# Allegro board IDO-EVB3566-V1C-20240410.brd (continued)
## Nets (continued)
PWM5_MIPI: M1.150(PWM5/SPI0_CS1_M0/UART0_RTSN/GPI) R49.2 U6.4(EN)
PWM6_OUT: D45.2 D45.9 J31.4 M1.148(PWM6/SPI0_MISO_M0/GPIO0_C5_D)
PWM7_IR: D45.1 D45.10 J31.2 M1.151(PWM7_IR/SPI0_CS0_M0/GPIO0_C6_D)
RECOVERY_KEY: C33.2 D5.1(I/O2) R25.2 SW4.3
RESETN: D82.2 D82.9 J46.3 M1.222(RESETN) R1231.2
RMII_CLK_: R1224.2 U11.15(TXC)
RMII_CLK_CTL: R1214.1 U11.12(RXD3/CLK_CTL)
RMII_RST_: C384.2 R1201.2 R1202.1 U11.21(PHYRSTB)
RN: D81.1 U11.6(MDI1-) U23.1(TD+)
RP: D81.3 U11.5(MDI1+) U23.3(TD-)
RXD0: R1206.1 U11.9(RXD0)
RXD1: R1205.1 R1215.1 U11.10(RXD1)
RXDV: R1213.1 U11.8(RXDV)
RXN: J12.6(RX-) U23.16(TX+)
RXP: J12.3(RX+) U23.14(TX-)
S0_RX: D43.1 D43.10 J42.2 R184.2 U22.13(R1IN)
S0_TX: D43.2 D43.9 J42.3 R183.2 U22.14(T1OUT)
S5_RX: D43.4 D43.7 J43.2 R186.2 U22.8(R2IN)
S5_TX: D43.5 D43.6 J43.3 R185.2 U22.7(T2OUT)
S7_RX: J40.2 R174.2 U21.13(R1IN)
S7_TX: J40.3 R173.2 U21.14(T1OUT)
S9_RX: J41.2 R176.2 U21.8(R2IN)
S9_TX: J41.3 R175.2 U21.7(T2OUT)
SARADC_VIN0/RECOVERY: M1.164(SARADC_VIN0/RECOVERY) R25.1
SARADC_VIN1: D82.4 D82.7 J46.4 M1.231(SARADC_VIN1)
SARADC_VIN2: D82.5 D82.6 J46.5 M1.165(SARADC_VIN2)
SDMMC0_CLK_: C155.2 D34.1 D34.10 J21.5(CLK) R160.2
SDMMC0_CLK_SD: M1.37(SDMMC0_CLK/TEST_CLKOUT/UART5_TX) R160.1
SDMMC0_CMD_SD: D33.4 D33.7 J21.3(CMD) M1.33(PWM10_M1/SDMMC0_CMD/UART5_RX_M0)
SDMMC0_D0_SD: D34.2 D34.9 J21.7(DATA0) M1.35(PWM8_M1/SDMMC0_D0/UART2_TX_M1/U)
SDMMC0_D1_SD: D34.4 D34.7 J21.8(DATA1) M1.32(PWM9_M1/SDMMC0_D1/UART2_RX_M1/U)
SDMMC0_D2_SD: D33.1 D33.10 J21.1(DATA2) M1.36(SDMMC0_D2/ARM_JTAG_TCK/UART5_CT)
SDMMC0_D3_SD: D33.2 D33.9 J21.2(CD/DATA3) M1.34(SDMMC0_D3/ARM_JTAG_TMS/UART5_RT)
SDMMC0_DET_L_SD: D34.5 D34.6 J21.9(CD) M1.163(SDMMC0_DET/SATA_CP_DET/GPIO0_A4) R344.2
SDMMC1_CLK_WIFI: M1.49(UART9_TX_M0/SDMMC1_CLK/GPIO2_B0) R67.1
SDMMC1_CMD_WIFI: M1.54(UART9_RX_M0/SDMMC1_CMD/GPIO2_A7) R66.2 U10.16(SDIO_DATA_CMD)
SDMMC1_D0_WIFI: M1.51(UART6_RX_M0/SDMMC1_D0/GPIO2_A3_) R65.2 U10.18(SDIO_DATA_0)
SDMMC1_D1_WIFI: M1.50(UART6_TX_M0/SDMMC1_D1/GPIO2_A4_) U10.19(SDIO_DATA_1)
SDMMC1_D2_WIFI: M1.55(UART7_RX_M0/SDMMC1_D2/GPIO2_A5_) U10.14(SDIO_DATA_2)
SDMMC1_D3_WIFI: M1.48(UART7_TX_M0/SDMMC1_D3/GPIO2_A6_) U10.15(SDIO_DATA_3)
SPI3_CLK_M1_OUT: D44.1 D44.10 J31.1 M1.206(PWM14_M1/SPI3_CLK_M1/I2S3_MCLK_)
SPI3_CS0_M1_OUT: D44.5 D44.6 J31.7 M1.201(PWM13_M1/SPI3_CS0_M1/SATA0_ACT_)
SPI3_MISO_M1_OUT: D44.4 D44.7 J31.5 M1.202(PWM12_M1/SPI3_MISO_M1/SATA1_ACT)
SPI3_MOSI_M1_OUT: D44.2 D44.9 J31.3 M1.204(PWM15_IR_M1/SPI3_MOSI_M1/I2S3_S)
SYS_LED_H: M1.69(ISP_FLASHTRIGOUT/EBC_SDCE0/GMAC) R415.2 R1227.1
TN: D81.4 U11.4(MDI0-) U23.6(RD+)
TP: D81.6 U11.3(MDI0+) U23.8(RD-)
TP1_INT: D18.2 D18.9 J8.5 J9.3 R44.2
TP1_RST: D18.1 D18.10 J8.4 J9.2 R43.2
TP1_SCL: D18.4 D18.7 J8.6 J9.4 R41.2 R42.1
TP1_SDA: D18.5 D18.6 J8.7 J9.5 R39.2 R40.1
TXN: J12.2(TX-) U23.11(RX+)
TXP: J12.1(TX+) U23.9(RX-)
UART0_RX: M1.157(PWM1_M0/GPUAVS/UART0_RX/GPIO0_C) R184.1 R189.1
UART0_TX: M1.156(PWM2_M0/NPUAVS/UART0_TX/MCU_JTA) R183.1 U22.11(T1IN)
UART1_CTSN_M0_WIFI: M1.39(SPI1_MISO_M0/UART1_CTSN_M0/GPIO) R69.1 U10.41(UART_RTS_N)
UART1_RTSN_M0_WIFI: M1.40(SPI1_CLK_M0/UART1_RTSN_M0/GPIO2) U10.44(UART_CTS_N)
UART1_RX_M0_WIFI: M1.47(UART1_RX_M0/GPIO2_B3_U) U10.42(UART_TXD)
UART1_TX_M0_WIFI: M1.46(UART1_TX_M0/GPIO2_B4_U) U10.43(UART_RXD)
UART2_RX_M0_DEBUG: M1.153(UART2_RX_M0_DEBUG/GPIO0_D0_U) R161.1
UART2_TX_M0_DEBUG: M1.152(UART2_TX_M0_DEBUG/GPIO0_D1_U) R162.1
UART5_RX_M1: M1.80(VOP_BT1120_D15/SPI1_CLK_M1/UART) R186.1 R190.1
UART5_TX_M1: M1.81(VOP_BT1120_D14/SPI1_MISO_M1/UAR) R185.1 U22.10(T2IN)
UART7_RX_M2: M1.73(CIF_D13/EBC_SDDO13/GMAC1_RXCLK_) R174.1 R178.1
UART7_TX_M2: M1.62(CIF_D12/EBC_SDDO12/GMAC1_RXD3_M) R173.1 U21.11(T1IN)
UART9_RX_M2: M1.71(CIF_D15/EBC_SDDO15/GMAC1_TXD1_M) R176.1 R177.1
UART9_TX_M2: M1.61(CIF_D14/EBC_SDDO14/GMAC1_TXD0_M) R175.1 U21.10(T2IN)
USB3_HOST1_DM: M1.16(USB_HOST1_DM) R124.1
USB3_HOST1_DM_2: D28.2(I/O1) J16.2(D-) R124.2
USB3_HOST1_DP: M1.17(USB_HOST1_DP) R126.1
USB3_HOST1_DP_2: D29.1(I/O2) J16.3(D+) R126.2
USB3_HOST1_SSRXN: M1.14(USB3_HOST1_SSRXN/SATA1_RXN) R127.1
USB3_HOST1_SSRXP: M1.15(USB3_HOST1_SSRXP/SATA1_RXP) R128.1
USB3_HOST1_SSTXN: C125.1 M1.12(USB3_HOST1_SSTXN/SATA1_TXN)
USB3_HOST1_SSTXP: C126.1 M1.13(USB3_HOST1_SSTXP/SATA1_TXP)
USB3_HOST1SSRXN: D30.1 D30.10 J16.5(SSRX-) R127.2
USB3_HOST1SSRXP: D30.2 D30.9 J16.6(SSRX+) R128.2
USB3_HOST1SSTXN: C125.2 D30.4 D30.7 J16.8(SSTX-)
USB3_HOST1SSTXP: C126.2 D30.5 D30.6 J16.9(SSTX+)
USB_HOST2_DM: M1.101(USB_HOST2_DM) R325.1
USB_HOST2_DM_: D46.1(I/O2) J39.2 R325.2
USB_HOST2_DP: M1.102(USB_HOST2_DP) R326.1
USB_HOST2_DP_: D47.1(I/O2) J39.3 R326.2
USB_HOST3_DM: M1.99(USB_HOST3_DM) R299.1
USB_HOST3_DP: M1.100(USB_HOST3_DP) R298.1
USB_OTG0_DM: M1.20(USB_OTG0_DM) R116.1
USB_OTG0_DM_2: D26.2(I/O1) J15.2(DATA+) R116.2
USB_OTG0_DP: M1.21(USB_OTG0_DP) R118.1
USB_OTG0_DP_2: D27.1(I/O2) J15.3(DATA-) R118.2
USB_OTG0_ID: M1.18(USB_OTG0_ID) Q5.3(DRAIN)
USB_OTG0_VBUSDET: M1.19(USB_OTG0_VBUSDET) R120.2 R121.1 R123.2
VOLN: C193.1 J25.4 L22.2
VOLP: C192.1 J25.3 L21.2
VORN: C198.1 J25.2 L24.2
VORP: C197.1 J25.1 L23.2
WIFI1T1R_CLK: C76.2 R67.2 U10.17(SDIO_DATA_CLK)
WIFI1T1R_XTAL_IN: C78.1 U10.10(XTAL_IN) XT2.3
WIFI1T1R_XTAL_OUT: R68.2 U10.11(XTAL_OUT)
WIFIBT_32KIN_1T1R: R73.2 R74.2 U10.24(LPO)
N17053074: C77.2 C79.2 U10.2(WL_BT_ANT)
N17053234: C77.1 C80.2 J11.2(SIG)
N19277328: C181.2 U22.1(C1+)
N19277330: C181.1 U22.3(C1-)
N19277334: C182.2 U22.4(C2+)
N19277336: C182.1 U22.5(C2-)
N19277340: C183.2 U22.2(V+)
N19277344: C184.2 U22.6(V-)
N19354508: C394.1 R63.1 R64.2 U9.4(ADJ)
N19356461: R56.1 R57.2 U7.4(ADJ)
N19357233: R59.1 R60.2 U8.4(ADJ)
N19781253: C176.2 U21.1(C1+)
N19781255: C176.1 U21.3(C1-)
N19781259: C177.2 U21.4(C2+)
N19781261: C177.1 U21.5(C2-)
N19781265: C178.2 U21.2(V+)
N19781269: C179.2 U21.6(V-)
N19781407: R177.2 U21.9(R2OUT)
N20037713: R178.2 U21.12(R1OUT)
N20144283: R189.2 U22.12(R1OUT)
N20144293: R190.2 U22.9(R2OUT)
N67159131: R136.1 U15.3(OCB)
N68563646: C30.2 U5.1(OSCI) XT1.2
N68563661: C31.2 U5.2(OSCO) XT1.1
N68693421: R148.1 U17.3(OCB)
N68696061: R153.1 U18.3(OCB)
N68696295: R158.1 U19.3(OCB)
N69227462: C397.2 R5.2 R7.2 U1.5(EN)
N69227513: C6.1 R3.1 R8.2 U1.6(FB)
N69227900: L3.1 U3.3(SW)
N69227918: R10.1 R12.2 U3.5(FB)
N69724413: R11.2 U3.1(EN)
N69863572: C81.2 R68.1 XT2.1
N69864462: C90.2 C91.2 L6.2 U10.23(VIN_LDO)
N69864477: L6.1 U10.21(VIN_LDO_OUT)
N69911722: R48.2 U6.3(FB)
N69911786: C53.2 J8.17 R38.2
N69912226: D23.A L5.2 U6.1(LX)
N69966336: J12.12(LEDG-) R1210.2
N69966774: C2.1 L1.1 U1.2(LX)
N69967080: C2.2 U1.4(BS)
N70130938: C388.2 U11.29(DVDD10OUT)
N70266506: J12.9(LEDY+) R1211.2
N70266836: R1203.1 U11.19(TXD3)
N70527306: D35.2(I/O1) J22.1 R161.2
N70527342: D36.2(I/O1) J22.2 R162.2
N70531034: D12.C R32.1 R34.1
N70572735: C185.2 J31.9 R195.2 R196.2
N70591036: R6.2 U2.5(EN)
N70591050: C3.1 L2.1 U2.2(LX)
N70591060: C13.1 R4.1 R9.2 U2.6(FB)
N70591176: C3.2 U2.4(BS)
N70593664: C61.1 J9.1 R46.2 R47.2
N70626310: M1.57(CAM_CLKOUT0/EBC_SDCE1/GMAC1_RXD) R16.2
N70633183: R129.2 U14.3(OCB)
N70633229: R122.2 U13.3(OCB)
N70633628: Q5.1(GATE) R117.1 R119.1
N70648039: C159.2 D38.1(I/O2) J34.5(L-COM) R164.1 R166.2
N70649018: C161.2 R169.2 R170.1
N70649944: C158.2 R163.2 R167.2
N70663154: R14.1 U4.4(EN)
N70663167: R1220.2 U4.3(OCB)
N70672743: C186.2 U24.2(BYPASS)
N70672808: C187.2 R197.1
N70672810: R197.2 U24.3(INP)
N70672945: C188.2 R198.1
N70672947: R198.2 U24.4(INN)
N70673300: L21.1 U24.8(VOP)
N70673587: L22.1 U24.5(VON)
N70674127: C194.2 U25.2(BYPASS)
N70674131: C195.2 R200.1
N70674133: R200.2 U25.3(INP)
N70674155: C196.2 R201.1
N70674157: R201.2 U25.4(INN)
N70674204: L23.1 U25.8(VOP)
N70674215: L24.1 U25.5(VON)
N70676752: R295.2 U26.8(RREF)
N70676766: R301.1 U26.25(OVCUR1#)
N70676768: R300.1 U26.24(OVCUR2#)
N70676770: R293.1 U26.23(PGANG)
N70676772: R294.1 U26.22(PSELF)
N70676774: R292.1 U26.19(OVCUR4#)
N70676824: R302.1 U26.20(OVCUR3#)
N70676921: R296.2 U26.5(AVDD/NC#5)
N70676923: R297.2 U26.9(AVDD/NC#9)
N70708323: R327.1 U27.3(OCB)
N70802303: C371.2 U23.7(CT2)
N70802422: C372.2 U23.2(CT1)
N70802644: R1229.1 U23.10(CT3)
N70803761: R1228.1 U23.15(CT4)
N70846219: R1207.1 U11.1(RSET)
N70854426: R1221.2 U7.3(EN) U8.3(EN) U9.3(EN)
N70857622: LED3.1(+) R19.2
N70857637: LED3.2(-) Q10.3(DRAIN)
N70857653: Q10.1(GATE) R1227.2
N70869941: C396.2 R1228.2
N70869956: C395.2 R1229.2
N70885563: J7.4 R1230.2
N70966122: R231.2 R232.1 U28.3(VCC)
N70966143: D86.A R1231.1 U28.2(RSET#)
N76750177: C385.2 U11.2(AVDD100UT)

Pads without a net: D33 5 6; D81 5; HOLE2 1; HOLE3 1; HOLE4 1; J5 1 7 30; J6 14; J7 1 5 6 7 23 24 26 27 29 30 34 37; J8 3 8 12 13 14 15 35 40; J12 4 5 7 8; J34 6; LED3 3; M1 1 2 3 4 5 6 24 25 26 27 56 90 91 95 96 97 98 103 104 173 174 175 177 178 179 183 184 185 189 190 191 193 194 195 203 207 208 209 210 214 219 220 221 227 230 234 235 236 237; MARK1 1; MARK2 1; MARK3 1; MARK4 1; U5 3 7; U10 4 5 8 29 30 32 35 37 38 39 40 45 46 47; U11 13 18 27; U23 4 5 12 13; U26 18 26

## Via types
v1: diameter 0.55, hole 0.3, TOP to BOTTOM, 1211 vias

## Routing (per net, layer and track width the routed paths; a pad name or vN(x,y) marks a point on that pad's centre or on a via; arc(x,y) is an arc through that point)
GND: length 1029.8
  TOP w0.127: v1(85.22,10.41) 85.22,9.78 84.96,9.53 81.03,9.53 80.78,9.77 v1(80.78,12.2) ; v1(62.74,53.21) 62.87,53.21 64.3,54.65 66.71,54.65 66.8,54.74 66.8,63.3 69.07,65.57 v1(69.47,65.57) 69.51,65.53 84.87,65.53 86.14,66.8 v1(87.96,66.8) ; v1(83.74,56.11) 83.64,56 83.64,55.88 82.56,54.8 81.69,54.8 79.22,52.34 v1(79.22,51.31) ; v1(77.34,41.66) 77.09,41.91 77.09,43.95 77,44.05 77,44.43 77.09,44.52 77.09,46.74 77.41,47.05 77.41,47.27 77.9,47.76 78.12,47.76 79.17,48.82 v1(79.17,49.68) ; C81.1 80.59,48.01 80.24,48.01 79.83,48.41 79.76,48.41 v1(79.76,51.69) 79.76,52.51 80.2,52.96 83.95,52.96 84.08,52.82 84.08,49.28 v1(83.44,48.64) ; v1(64.6,52.87) 64.6,53.06 65.28,53.73 67.09,53.73 67.75,54.4 67.75,62.96 69.07,64.28 85.16,64.28 85.86,64.98 86.87,64.98 87.68,65.79 88.39,65.79 89.03,65.15 90.54,65.15 v1(91.18,65.79) ; v1(19.01,7.83) 19.1,7.92 19.1,10.13 18.81,10.42 18.79,10.42 v1(18.79,10.47) 18.74,10.52 17.09,10.52 16.87,10.29 v1(16.73,10.29) 16.47,10.54 14.96,10.54 14.61,10.19 v1(14.61,10.16) 14.32,10.44 12.6,10.44 12.32,10.16 v1(12.32,10.06) 12.32,7.9 12.62,7.59 13.19,7.59 13.57,7.21 J5.29 ; 71.75,56.64 71.76,56.64 71.76,60.75 v1(71.97,60.96)
  TOP w0.305: J8.11 49.58,7.59 v1(49.38,7.8) ; J5.23 v1(16.57,7.69) ; J8.22 44.08,7.34 43.67,7.75 v1(43.31,7.75) ; v1(82.84,4.64) 82.83,4.65 82.83,5.59 83.05,5.8 J7.19 ; v1(19.01,7.83) 18.5,7.83 18.07,7.4 J5.20 ; J8.28 41.08,5.97 41.61,5.44 v1(41.98,5.44) ; J6.5 v1(79.98,62.43) ; J6.2 v1(78.48,62.34) ; J6.11 v1(82.98,62.49) ; J8.25 42.58,7.76 v1(42.62,7.8) ; J8.31 v1(39.58,5.65) ; J6.17 v1(85.98,62.64) ; J5.29 v1(13.57,5.61) ; v1(62.73,8.4) 62.38,8.04 J9.6 ; J6.8 v1(81.48,62.5) ; J5.26 v1(15.07,7.7)
  TOP w0.381: v1(20.64,17.74) 20.11,17.21 19.81,17.21 ; R199.1 v1(78.71,31.14) ; v1(95.12,25.02) D32.3 D32.8 ; M1.170 72.69,48.06 v1(72.34,48.41) ; C298.1 88.6,21.21 88.74,21.06 v1(88.95,21.06) ; D44.8 D44.3 v1(10.92,17.91) ; v1(93.6,35.81) 93.47,35.69 D47.2 ; v1(10.79,14.73) D45.3 D45.8 ; v1(91.18,65.79) R165.1 ; U10.36 v1(93.69,38.32) ; v1(26.85,31.52) 27.03,31.7 27.03,32.64 26.6,33.06 M1.192 26.17,32.65 26.17,31.62 v1(25.96,31.41) ; C198.2 89,28.54 89,29.08 v1(88.98,29.11) 89.15,29.29 C193.2 ; C76.1 77.55,41.86 v1(77.34,41.66) ; v1(85.22,10.41) 85.21,10.4 XT5.2 ; v1(11.56,25.65) 11.87,25.34 R12.1 ; v1(51.31,15.11) 51,15.42 49.66,15.42 48.85,14.61 M1.205 47.82,15.32 v1(47.82,15.96) ; v1(79.22,58.06) D6.8 D6.3 ; C333.1 79.91,23.04 79.53,22.66 v1(79.53,22.56) ; v1(94.07,31.5) 93.72,31.14 D46.2 ; D31.8 D31.3 95.1,28.55 v1(95.12,28.57) ; C196.1 77.44,24.57 v1(77.37,24.64) ; v1(83.44,48.64) 83.12,48.96 C78.2 82.68,49.53 83.24,50.09 XT2.2 ; U25.7 84.72,27.12 v1(84.67,27.18) 84.64,27.2 ; D7.3 D7.8 v1(82.22,58.17) ; C186.1 79.09,30.18 v1(78.74,30.52) ; v1(12.45,12.32) 12.54,12.41 C185.1 ; J16.4 v1(40.31,60.07) ; C194.1 79.1,27.18 78.78,26.87 v1(78.76,26.87) ; v1(26.82,49.61) 26.85,49.58 26.85,48.78 M1.187 26.08,49.01 v1(26.08,49.66) ; v1(45.01,47.46) 45.01,48.09 M1.181 44.24,48.17 v1(44.24,47.46) ; D39.2 v1(91.14,64.39) ; XT2.4 80.15,52.08 v1(79.76,51.69) ; v1(30.05,49.73) 30.05,48.98 M1.186 29.39,48.7 v1(29.39,49.76) ; v1(20.32,45.97) C62.1 R17.1 ; U24.7 84.41,30.42 v1(84.22,30.61) ; D30.3 D30.8 v1(43.56,56.91) 43.31,57.16 J16.7
  TOP w0.635: 101.46,39.58 J39.4 ; J39.4 103.01,39.58 ; J39.4 102.23,40.35 ; J39.4 102.23,38.8 ; 102.23,17.46 J38.4 ; J38.4 101.46,18.24 ; J38.4 102.23,19.02 ; J38.4 103.01,18.24 ; J42.4 3.57,42.97 ; J42.4 2.79,42.2 ; J42.4 2.79,43.75 ; 96.77,38.8 J36.4 ; J36.4 97.55,39.58 ; J36.4 96,39.58 ; J13.4 103.01,28.91 ; J13.4 101.46,28.91 ; J13.4 102.23,28.13 ; J13.4 102.23,29.69 ; J1.2 11.04,63.11 ; J1.2 10.06,61.43 ; J1.2 12.02,61.43 ; J1.2 11.04,59.75 ; 88.8,61.21 J6.20 ; J6.20 89.73,59.28 ; J6.20 89.73,63.14 ; 2.79,20.86 J41.4 2.79,22.42 ; 8.11,63.87 J2.2 ; J2.2 8.89,64.64 ; J2.2 7.33,64.64 ; J2.2 8.11,65.42 ; J2.1 10.89,64.64 ; J2.1 10.11,65.42 ; J2.1 9.33,64.64 ; J2.1 10.11,63.87 ; J40.4 3.57,10.97 ; J40.4 2.79,11.75 ; J40.4 2.79,10.19 ; J40.4 2.02,10.97 ; J6.23 89.73,68.6 ; J6.23 90.66,67.17 ; J6.23 88.8,67.17 ; 2.19,67.2 J1.6 ; J1.6 1.51,68.63 ; J1.6 2.87,68.63 ; 2.79,31.53 J43.4 2.79,33.08 ; 74.3,61.21 J6.21 76.16,61.21 ; J6.22 76.16,67.17 ; J6.22 75.23,65.74 ; J6.22 75.23,68.6 ; J6.22 74.3,67.17 ; 4.86,61.43 J1.3 ; J1.3 5.84,63.11 ; J1.3 6.82,61.43 ; J1.3 5.84,59.75 ; J1.5 12.67,68.63 ; J1.5 11.31,68.63 ; J1.5 11.99,67.2
  L2_GND w0.635: 2.02,10.97 J40.4 ; J40.4 2.79,10.19 ; J40.4 2.79,11.75 ; J40.4 3.57,10.97 ; J1.3 5.84,63.11 ; J1.3 6.82,61.43 ; J1.3 5.84,59.75 ; J1.3 4.86,61.43 ; 10.11,63.87 J2.1 ; J2.1 9.33,64.64 ; J2.1 10.11,65.42 ; J2.1 10.89,64.64 ; J1.2 11.04,63.11 ; J1.2 10.06,61.43 ; J1.2 12.02,61.43 ; J1.2 11.04,59.75 ; 11.99,67.2 J1.5 ; J1.5 12.67,68.63 ; J1.5 11.31,68.63 ; J6.20 90.66,61.21 ; J6.20 89.73,63.14 ; J6.20 89.73,59.28 ; J6.20 88.8,61.21 ; 2.79,42.2 J42.4 ; J42.4 3.57,42.97 ; J42.4 2.02,42.97 ; J42.4 2.79,43.75 ; J6.23 89.73,68.6 ; J6.23 89.73,65.74 ; J6.23 90.66,67.17 ; J6.23 88.8,67.17 ; 74.3,61.21 J6.21 ; J6.21 76.16,61.21 ; J6.21 75.23,63.14 ; 8.11,63.87 J2.2 ; J2.2 8.89,64.64 ; J2.2 7.33,64.64 ; J2.2 8.11,65.42 ; 96.77,28.13 J37.4 ; J37.4 96.77,29.69 ; J37.4 97.55,28.91 ; J37.4 96,28.91 ; J43.4 3.57,32.31 ; J43.4 2.79,33.08 ; J43.4 2.02,32.31 ; J43.4 2.79,31.53 ; J41.4 3.57,21.64 ; J41.4 2.79,22.42 ; J41.4 2.79,20.86 ; J41.4 2.02,21.64 ; 101.46,28.91 J13.4 ; J13.4 102.23,29.69 ; J13.4 103.01,28.91 ; J13.4 102.23,28.13 ; J36.4 96.77,40.35 ; J36.4 96.77,38.8 ; J36.4 97.55,39.58 ; J36.4 96,39.58 ; 6.33,12.19 J31.10 ; J31.10 7.14,11.38 ; J31.10 7.14,13.01 ; J31.10 7.96,12.19 ; 1.51,68.63 J1.6 ; J1.6 2.87,68.63 ; J1.6 2.19,67.2 ; J6.22 75.23,68.6 ; J6.22 75.23,65.74 ; J6.22 76.16,67.17 ; J6.22 74.3,67.17 ; 101.46,18.24 J38.4 ; J38.4 102.23,19.02 ; J38.4 103.01,18.24 ; J38.4 102.23,17.46 ; 101.46,39.58 J39.4 ; J39.4 103.01,39.58 ; J39.4 102.23,40.35 ; J39.4 102.23,38.8
  L3_S2 w0.635: 7.96,12.19 J31.10 7.14,13.01 ; 2.79,10.19 J40.4 2.02,10.97 ; 102.23,17.46 J38.4 ; J38.4 101.46,18.24 ; J38.4 103.01,18.24 ; J38.4 102.23,19.02 ; 75.23,65.74 J6.22 ; J6.22 74.3,67.17 ; J6.22 75.23,68.6 ; J6.22 76.16,67.17 ; J42.4 3.57,42.97 ; J42.4 2.79,42.2 ; J42.4 2.79,43.75 ; J42.4 2.02,42.97 ; 89.73,59.28 J6.20 ; J6.20 88.8,61.21 ; J6.20 89.73,63.14 ; J6.20 90.66,61.21 ; 1.51,68.63 J1.6 2.87,68.63 ; 102.23,28.13 J13.4 ; J13.4 102.23,29.69 ; J13.4 103.01,28.91 ; J13.4 101.46,28.91 ; 88.8,67.17 J6.23 ; J6.23 89.73,68.6 ; J6.23 90.66,67.17 ; J6.23 89.73,65.74 ; 101.46,39.58 J39.4 ; J39.4 102.23,40.35 ; J39.4 102.23,38.8 ; J39.4 103.01,39.58 ; 96.77,38.8 J36.4 ; J36.4 96.77,40.35 ; J36.4 97.55,39.58 ; J36.4 96,39.58 ; 74.3,61.21 J6.21 ; J6.21 76.16,61.21 ; J6.21 75.23,63.14 ; 11.31,68.63 J1.5 12.67,68.63
  BOTTOM w0.127: 72.86,17.94 46.8,17.94 v1(45.84,16.98) 45.26,16.98 39.18,10.9 38.66,10.9 v1(38.55,10.79) ; 17.53,51.24 16.33,50.05 16.33,45.42 17.35,44.4 20.45,44.4 21.11,43.74 21.11,41.71 20.75,41.35 20.75,38.63 21.04,38.35 21.04,35.81 21.44,35.41 ; v1(40.26,38.73) 40.05,38.52 34.88,38.52 34.8,38.61 ; v1(18.79,10.47) 18.83,10.47 19.03,10.67 22.41,10.67 23.07,11.33 36.86,11.33 37.39,11.86 39.08,11.86 45.76,18.54 v1(45.85,18.54) 45.98,18.68 66.04,18.68 66.24,18.87 66.37,18.87 ; 66.37,18.87 66.44,18.94 66.98,18.94 67.08,18.84 ; 66.37,18.87 v1(66.37,18.89) ; v1(65.87,30.5) 66.12,30.25 66.12,28.62 66.29,28.45 68.71,28.45 68.83,28.57 68.83,30.45 68.78,30.5 v1(68.78,30.84) 68.78,30.94 68.8,30.95 C31.1 69.01,31.59 69.01,31.98 v1(69.22,32.18) 69.22,32.26 69.01,32.46 69.01,33.76 68.86,33.91 65.35,33.91 65.24,33.8 65.24,31.13 v1(65.87,30.5) ; v1(65.87,30.5) C30.1 ; v1(35.69,30.48) 35.69,31.94 36.04,32.3 40.11,32.3 40.26,32.15 40.26,28.96 40.13,28.83 38.48,28.83 37.72,28.07 v1(37.72,27.94) ; v1(64.03,43.54) 64.03,43.54 63.76,43.54 63.32,43.09 56.73,43.09 56.54,43.29 54.02,43.29 53.22,44.08 50.65,44.08 v1(50.43,44.3) 50.13,44.3 49.34,45.09 42.46,45.09 42.16,45.39 39.85,45.39 38.98,44.52 37.68,44.52 37.02,43.86 35.88,43.86 33.92,41.9 33.5,41.9 33.01,41.41 33.01,40.49 32.13,39.6 32.13,39.11 31.65,38.63 31.15,38.63 30.47,37.94 30.47,37.35 30.86,36.96 31.23,36.96 32.88,38.61 34.8,38.61 ; v1(77.34,41.66) 77.22,41.53 75.9,41.53 ; v1(79.36,44.13) 78.58,43.35 69.66,43.35 69.26,43.74 67.52,43.74 67.18,43.4 65.84,43.4 65.68,43.56 v1(64.8,43.56) ; 74.88,42.33 69.23,42.33 68.84,42.72 67.94,42.72 67.61,42.39 65.67,42.39 65.15,41.87 ; v1(67.08,18.89) 67.08,18.84 ; 67.08,18.84 67.26,18.84 67.43,18.68 69.29,18.68 69.53,18.92 69.93,18.92 70.01,18.85 v1(70.01,18.89) ; 66.71,39.65 66.85,39.65 67.27,39.23 71.37,39.23 74.65,35.94 84.33,35.94 85.8,34.47 v1(85.8,34.26) ; 66.71,39.65 67.32,40.26 73.15,40.26 75.95,37.47 v1(82.83,37.47) 84.31,37.47 87.61,34.16 v1(88.57,34.16) 88.57,34 89,33.57 90.1,33.57 90.53,34 v1(90.53,34.29) 90.53,34.44 89.61,35.36 87.76,35.36 v1(86.41,36.7) v1(85.41,37.71) 84.38,38.73 v1(84.08,38.73) v1(82.5,38.73) v1(79.88,38.73) 76.69,38.73 74.42,41 66.31,41 65.69,40.39 56.21,40.39 55.59,41 50.19,41 48.46,42.73 41.22,42.73 v1(41.05,42.9) 40.59,42.9 39.88,42.19 38.61,42.19 37.97,41.55 36.98,41.55 36.07,40.64 36.07,39.88 34.8,38.61 ; 66.71,39.65 55.61,39.65 v1(55.38,39.88) 55.14,40.11 48.98,40.11 47.61,41.49 v1(47.24,41.49) 47.03,41.27 42.42,41.27 42.16,41.02 41.78,41.02 41.58,41.22 38.45,41.22 38.18,40.95 38.18,40.28 38.33,40.13 39.12,40.13 39.3,40.32 43,40.32 v1(43.23,40.56) 43.39,40.71 47.67,40.71 48.86,39.52 51.44,39.52 51.67,39.28 v1(54.24,39.28) 54.66,39.28 54.87,39.07 66.41,39.07 v1(66.55,38.93) 66.76,38.72 70.86,38.72 74.15,35.43 83.95,35.43 84.4,34.98 v1(84.4,34.34) ; C155.1 37.25,48.02 v1(37.35,48.02) ; v1(45.72,25.48) 45.72,29.59 43.98,31.34 v1(42.74,31.34) 42.82,31.26 v1(42.82,29.84) 42.91,29.75 v1(42.91,28.22) 42.91,27.7 v1(43.43,27.18) 43.48,27.13 v1(43.48,23.16) v1(43.48,21.79) 43.48,20.47 37.08,14.07 30.05,14.07 29.56,13.58 21.19,13.58 v1(20.78,13.17) v1(20.04,13.17) v1(19.35,13.17) v1(18.67,13.17) 18.53,13.31 v1(17.78,13.31) 16.93,13.31 14.78,11.16 13.74,11.16 13.68,11.1 13.01,10.43 12.69,10.43 v1(12.32,10.06) 12.32,9.79 ; 65.88,41.88 65.15,41.15 56.53,41.15 55.91,41.76 52.48,41.76 v1(52.27,41.98) 51.89,42.35 49.92,42.35 48.7,43.56 41.83,43.56 41.53,43.87 40.48,43.87 39.61,43 38.34,43 37.65,42.31 36.67,42.31 35.23,40.87 35.23,40.28 34.83,39.88 34.37,39.88 34.12,40.13 34.12,40.48 36.48,42.84 37.47,42.84 38.13,43.51 39.4,43.51 40.27,44.38 41.74,44.38 42.04,44.07 48.92,44.07 49.92,43.07 52.5,43.07 v1(53.09,42.48) 53.3,42.27 56.12,42.27 56.52,41.87 v1(59.22,41.87) ; 74.34,20.62 72.4,18.68 71.11,18.68 70.99,18.8 70.87,18.8 v1(70.87,18.89)
  BOTTOM w0.305: v1(60.33,7.75) 60.17,7.59 J10.16 ; v1(66.04,60.83) 66.56,61.35 Q5.2 ; v1(62.73,8.4) 63.17,7.96 J10.22 ; v1(58.67,7.62) 58.67,7.62 J10.13 ; J10.10 57.17,7.5 57.07,7.6 v1(57.07,7.63) ; J10.19 v1(61.67,7.8)
  BOTTOM w0.381: v1(57.4,56.64) 57.78,56.26 R123.1 ; C392.1 28.07,25.07 v1(28.06,25.06) ; C61.2 71.24,8.53 72.14,8.53 v1(72.77,9.16) ; v1(35.69,30.48) 36.46,29.71 XT4.4 ; v1(17.02,23.75) 17.26,24 C175.1 ; C381.1 R1214.2 33.91,17.03 v1(34.25,16.68) ; v1(93.07,65.13) 93.1,65.1 93.15,65.1 93.34,64.9 C161.1 ; v1(85.85,53.34) 85.98,53.47 R30.1 ; C73.1 v1(82.84,4.64) ; v1(33.14,28.6) 32.97,28.43 C390.1 C389.1 ; v1(5.93,27.81) 6.54,28.42 C179.1 ; C383.1 29.29,18.48 v1(29.11,18.66) ; C388.1 R1212.2 30.84,28.01 v1(30.62,27.78) ; v1(37.72,27.94) 37.65,28.01 C386.2 ; v1(5.82,39.94) 6.83,39.94 D43.8 D43.3 8.2,40.01 v1(8.43,39.78) ; v1(39.88,25.81) 39.44,25.37 R1207.2 C385.1 ; v1(38.73,53.95) D34.8 D34.3 ; J21.6 40.85,54.11 v1(40.88,54.11) ; v1(28.08,35.31) 27.96,35.18 D81.2 ; J21.10 36.35,56.8 v1(37.08,57.53) ; R1217.1 27.46,28.01 v1(27.24,27.79) ; C183.1 12.26,32.16 12.92,32.82 13.46,32.82 v1(13.61,32.66) 13.87,32.92 U22.15 ; v1(86.87,57.15) 86.51,56.8 D8.2 D11.2 ; XT4.2 v1(38.32,31.51) ; D27.2 60.76,56.77 v1(60.51,57.02) ; v1(45.21,53.98) D33.8 D33.3 ; v1(81.28,3.17) 80.97,2.86 R57.1 ; v1(67.32,7.82) 67.44,7.93 D18.3 D18.8 ; U21.15 13.76,25.93 v1(13.55,25.72) ; R1209.1 29.66,28.01 v1(29.34,27.69) 29.01,28.01 C393.2 ; R1215.2 36.07,17.39 v1(35.69,17.01) ; v1(28.06,22.86) 28.31,23.11 C384.1 ; v1(7.54,38.1) 7.44,38 C184.1 ; v1(83.74,56.11) 83.69,56.16 D10.2 ; v1(39.93,22.1) 39.93,21.85 39.57,21.48 C380.1 ; D82.3 D82.8 5.94,30.94 v1(5.84,30.84) ; C372.1 v1(29.53,38.35) ; D26.1 v1(63.88,55.5) ; v1(53.34,54.36) 53.57,54.13 D29.2 ; C391.1 37.72,19.56 v1(37.47,19.81) ; C178.1 v1(9.29,23.48) ; C68.1 v1(86.06,4.64) ; C371.1 v1(21.9,38.3) ; R119.2 v1(71.97,60.96)
  BOTTOM w0.635: 74.3,67.17 J6.22 ; J6.22 75.23,65.74 ; J6.22 75.23,68.6 ; J6.22 76.16,67.17 ; 2.87,68.63 J1.6 1.51,68.63 ; J39.4 102.23,40.35 ; J39.4 101.46,39.58 ; J39.4 102.23,38.8 ; J39.4 103.01,39.58 ; J31.10 7.96,12.19 ; J31.10 7.14,11.38 ; J31.10 6.33,12.19 ; J31.10 7.14,13.01 ; 2.02,42.97 J42.4 ; J42.4 3.57,42.97 ; J42.4 2.79,43.75 ; J42.4 2.79,42.2 ; J13.4 103.01,28.91 ; J13.4 102.23,29.69 ; J13.4 102.23,28.13 ; J36.4 97.55,39.58 ; J36.4 96.77,38.8 ; J36.4 96.77,40.35 ; J36.4 96,39.58 ; 2.79,20.86 J41.4 ; J41.4 2.02,21.64 ; J41.4 2.79,22.42 ; J6.20 90.66,61.21 ; J6.20 88.8,61.21 ; J6.20 89.73,59.28 ; J38.4 102.23,19.02 ; J38.4 102.23,17.46 ; J38.4 103.01,18.24 ; 10.06,61.43 J1.2 ; J1.2 11.04,59.75 ; J1.2 12.02,61.43 ; 2.79,31.53 J43.4 ; J43.4 2.79,33.08 ; J43.4 3.57,32.31 ; J43.4 2.02,32.31 ; 76.16,61.21 J6.21 74.3,61.21 ; 12.67,68.63 J1.5 11.31,68.63 ; J6.23 90.66,67.17 ; J6.23 89.73,65.74 ; J6.23 88.8,67.17 ; J6.23 89.73,68.6 ; J40.4 3.57,10.97 ; J40.4 2.79,10.19 ; J40.4 2.02,10.97 ; J40.4 2.79,11.75 ; 96.77,28.13 J37.4 96,28.91
  vias: v1(0.69,48.36) v1(0.69,16.64) v1(0.69,12.83) v1(0.69,9.02) v1(0.69,5.21) v1(0.69,1.4) v1(0.84,68.78) v1(0.81,68) v1(0.76,50.6) v1(2.44,24.64) v1(2.49,35.31) v1(3.33,69.29) v1(3.3,68.33) v1(4.75,0.66) v1(4.95,69.22) v1(5.44,35.89) v1(5.92,46.66) v1(5.97,47.37) v1(5.97,42.67) v1(5.97,27.05) v1(5.97,26.16) v1(6.12,34.62) v1(6.1,23.07) v1(6.58,46.71) v1(7.11,69.22) v1(7.24,23.11) v1(7.32,46.74) v1(7.37,42.67) v1(7.75,67.69) v1(8.51,23.11) v1(8.56,0.66) v1(9.14,67.69) v1(9.27,43) v1(9.4,69.22) v1(9.42,48.39) v1(9.88,4.09) v1(10.11,3.17) v1(10.21,53.7) v1(10.24,26.7) v1(10.46,2.39) v1(10.85,69.27) v1(10.79,67.69) v1(11.05,35.43) v1(11.46,2.44) v1(11.68,35.94) v1(12.32,35.94) v1(12.37,0.66) v1(13.41,69.27) v1(13.36,67.69) v1(14.91,0.66) v1(15.36,15.65) v1(15.75,23.75) v1(16.18,15.65) v1(16.36,40.77) v1(16.39,40.01) v1(16.38,23.88) v1(16.79,43.92) v1(16.89,45.59) v1(16.93,40.77) v1(16.94,15.62) v1(17.02,46.99) v1(17,40.01) v1(17.14,30.62) v1(17.45,0.66) v1(17.53,49.02) v1(17.53,48.39) v1(17.53,46.35) v1(17.53,45.59) v1(18.11,49.02) v1(18.11,48.39) v1(18.11,34.82) v1(18.24,30) v1(18.31,22.45) v1(18.54,24.43) v1(18.54,23.75) v1(18.69,29.34) v1(19.76,3) v1(19.91,23.09) v1(19.94,22.07) v1(19.99,0.66) v1(20.07,30.23) v1(20.14,20.6) v1(20.09,19.94) v1(20.45,32.51) v1(20.68,16.08) v1(20.68,2.97) v1(21.79,2.95) v1(22.53,0.66) v1(22.76,21.56) v1(22.76,20.57) v1(22.89,3) v1(23.7,2.97) v1(25.07,0.66) v1(25.5,15.71) v1(25.48,15.14) v1(25.96,3.02) v1(26.16,15.7) v1(26.47,44.4) v1(26.57,3.02) v1(27.06,44.35) v1(27.61,0.66) v1(29.13,15.75) v1(29.59,44.53) v1(29.56,19.13) v1(29.92,15.72) v1(30.15,0.66) v1(30.33,44.53) v1(32.69,0.66) v1(32.77,24.13) v1(32.77,22.61) v1(32.77,21.08) v1(34.16,24.13) v1(34.29,22.61) v1(34.29,21.08) v1(34.57,3.2) v1(35.23,0.66) v1(35.66,69.29) v1(35.66,57.78) v1(35.69,22.61) v1(35.81,63.88) v1(35.81,29.24) v1(35.81,24.13) v1(35.81,21.08) v1(35.94,67.82) v1(36.52,10.79) v1(37.13,40.97) v1(37.42,5.54) v1(37.64,69.27) v1(37.77,0.66) v1(38.08,5.61) v1(38.23,60.07) v1(39.27,69.24) v1(40.26,54.1) v1(40.31,0.66) v1(40.64,67.31) v1(41.22,21.62) v1(41.4,64.14) v1(41.81,69.24) v1(41.91,62.23) v1(42.25,4.85) v1(42.8,38.59) v1(42.85,0.66) v1(43.31,60.91) v1(43.56,52.45) v1(43.69,50.16) v1(44.35,69.24) v1(44.45,67.31) v1(45.39,0.66) v1(45.97,64.14) v1(46.1,7.75) v1(46.74,7.75) v1(46.85,4.87) v1(46.85,4.11) v1(46.89,69.24) v1(47.22,25.22) v1(47.93,0.71) v1(48.26,67.31) v1(48.26,62.23) v1(48.64,57.4) v1(49.43,69.24) v1(50.14,13.54) v1(50.52,67.77) v1(50.55,63.63) v1(50.52,62.2) v1(50.47,0.66) v1(50.67,57.4) v1(51.19,57.66) v1(51.52,50.16) v1(51.97,69.24) v1(52.7,64.01) v1(52.7,62.99) v1(52.7,62.23) v1(52.83,57.01) v1(53.01,0.66) v1(53.11,65.96) v1(53.34,62.23) v1(53.34,59.11) v1(53.4,13.08) v1(53.55,50.16) v1(53.99,9.29) v1(54.51,69.24) v1(54.61,65.79) v1(54.86,56.9) v1(55.05,64.2) v1(55.5,56.9) v1(55.55,0.66) v1(56.13,8.56) v1(56.21,10.67) v1(56.64,57.53) v1(56.73,54.58) v1(56.75,68.22) v1(56.9,64.04) v1(56.9,63.46) v1(56.9,62.89) v1(56.9,58.8) v1(56.9,58.23) v1(57.05,69.24) v1(57,12.77) v1(57.26,52.7) v1(57.33,13.98) v1(57.68,68.2) v1(58.04,66.29) v1(58.04,8.64) v1(58.09,0.66) v1(58.4,54.1) v1(59.05,12.77) v1(59.21,36.73) v1(59.31,52.64) v1(59.42,4.48) v1(59.59,69.24) v1(59.56,54.23) v1(60.12,63.25) v1(60.63,0.66) v1(60.96,63.25) v1(60.95,46.99) v1(61.14,43.64) v1(61.53,47.01) v1(61.48,12.83) v1(61.82,43.64) v1(61.87,3.58) v1(62.13,69.24) v1(62.1,46.99) v1(62.28,59.45) v1(63.17,0.66) v1(63.8,3.28) v1(64,47.16) v1(64.14,68.33) v1(64.33,65.21) v1(64.67,69.24) v1(64.66,47.16) v1(65.28,13.46) v1(65.71,0.66) v1(66.95,21.77) v1(66.98,15.6) v1(67.21,69.24) v1(67.42,68.22) v1(67.67,15.57) v1(67.82,4.83) v1(68.25,0.71) v1(68.35,41.98) v1(68.39,4.83) v1(68.57,45.53) v1(69.29,54.08) v1(69.75,69.24) v1(69.9,55.22) v1(70.54,54.61) v1(70.48,50.19) v1(70.79,0.71) v1(71.12,32.03) v1(71.63,31.72) v1(71.6,14.78) v1(71.7,63.48) v1(71.96,62.97) v1(72.01,14.2) v1(72.21,26.44) v1(72.29,69.24) v1(72.37,3.17) v1(73.05,3.17) v1(73.15,11.81) v1(73.24,10.64) v1(73.33,0.71) v1(73.54,56.39) v1(73.73,3.17) v1(73.91,7.79) v1(74.02,47.68) v1(74.12,56.39) v1(74.47,16.74) v1(74.83,69.24) v1(75.05,56.39) v1(75.31,9.02) v1(75.36,16.74) v1(75.72,15.42) v1(75.75,10.41) v1(75.87,0.71) v1(76.35,52.65) v1(76.83,55.24) v1(77.17,49.56) v1(77.34,25.27) v1(77.34,9.03) v1(77.37,69.24) v1(77.37,5.59) v1(77.47,67.31) v1(77.65,28.7) v1(77.77,10.54) v1(77.85,12.54) v1(78.23,32.81) v1(78.41,0.71) v1(78.87,32.81) v1(79.25,5.56) v1(79.5,32.81) v1(79.63,3.45) v1(79.83,5.56) v1(79.91,69.24) v1(80.09,67.34) v1(80.26,12.7) v1(80.52,32.81) v1(80.64,47.45) v1(80.95,0.71) v1(81.03,5.59) v1(81.18,28.37) v1(82.3,40.64) v1(82.3,19.18) v1(82.3,17.27) v1(82.4,45.24) v1(82.55,67.31) v1(83.31,18.29) v1(83.49,0.71) v1(83.72,69.24) v1(84.07,5.16) v1(84.18,25.15) v1(84.2,18.08) v1(84.28,17.17) v1(84.43,3.89) v1(84.45,43.56) v1(84.45,19.18) v1(84.59,29.13) v1(84.58,25.55) v1(84.66,5.16) v1(84.98,25.13) v1(85.09,67.31) v1(85.14,45.19) v1(85.17,50.83) v1(85.45,28.5) v1(86.03,0.71) v1(86.26,69.24) v1(87.63,67.31) v1(87.6,5.56) v1(88.21,5.38) v1(88.54,41.1) v1(88.57,0.71) v1(88.67,43.51) v1(88.8,69.24) v1(88.87,5.41) v1(88.95,48.13) v1(89.34,47.68) v1(89.43,56.9) v1(89.41,55.63) v1(89.48,58.5) v1(89.53,16.89) v1(89.46,5.41) v1(90.04,49.02) v1(90.02,45.67) v1(90.04,17.4) v1(90.27,31.72) v1(90.73,45.69) v1(90.83,57.71) v1(90.75,56.21) v1(91.11,0.71) v1(91.19,54.13) v1(91.34,69.24) v1(91.34,15.21) v1(91.72,61.44) v1(91.74,52.15) v1(91.87,47.17) v1(92.23,46.33) v1(92.33,21.59) v1(92.43,16.69) v1(92.71,20.7) v1(92.79,46.81) v1(92.76,16) v1(92.94,48.97) v1(93.09,21.59) v1(93.17,16.69) v1(93.31,26.75) v1(93.5,52.17) v1(93.47,46.42) v1(93.47,15.98) v1(93.65,0.71) v1(93.73,13.21) v1(93.84,26.52) v1(93.88,69.24) v1(93.98,48.64) v1(93.98,45.87) v1(94.39,13.21) v1(94.39,12.45) v1(94.39,11.68) v1(94.39,10.92) v1(94.49,32) v1(94.61,48.13) v1(94.64,8.74) v1(94.74,53.67) v1(94.82,55.91) v1(95,49.02) v1(95.28,47.42) v1(95.66,50.04) v1(95.76,48.26) v1(95.79,45.34) v1(95.94,50.88) v1(96.06,17.22) v1(96.19,0.71) v1(96.34,47.42) v1(96.39,49.02) v1(96.37,45.31) v1(96.49,8.86) v1(96.95,48.23) v1(97.03,44.68) v1(97.28,44.16) v1(97.46,47.42) v1(97.66,49.02) v1(97.79,43.31) v1(97.92,44.83) v1(97.92,44.07) v1(97.97,18.52) v1(97.97,16) v1(98.22,48.21) v1(98.73,47.45) v1(98.73,0.71) v1(98.81,44.83) v1(98.81,44.07) v1(99.19,49.02) v1(99.19,42.67) v1(99.69,43.81) v1(100.2,42.67) v1(100.33,49.02) v1(100.46,43.81) v1(101.09,65.28) v1(101.09,63.88) v1(101.22,42.67) v1(101.35,49.02) v1(101.35,43.81) v1(101.27,0.71) v1(101.5,69.24) v1(102.23,65.79) v1(102.23,64.39) v1(102.23,63.12) v1(102.23,43.84) v1(102.23,42.55) v1(102.49,45.09) v1(102.49,44.45) v1(102.54,0.71) v1(102.62,48.9) v1(102.62,47.37) v1(103.23,47.9) v1(103.2,46.94) v1(103.23,45.57) v1(103.38,69.22) v1(103.38,44.58) v1(103.5,42.42) v1(103.71,51.13) v1(103.76,2.01) v1(104.37,68.25) v1(104.37,65.74) v1(104.37,63.2) v1(104.37,60.66) v1(104.37,58.12) v1(104.37,55.58) v1(104.37,53.04) v1(104.37,50.5) v1(104.37,47.96) v1(104.37,46.69) v1(104.37,45.42) v1(104.37,44.15) v1(104.37,42.88) v1(104.37,41.61) v1(104.37,39.07) v1(104.37,36.53) v1(104.37,33.99) v1(104.37,31.45) v1(104.37,28.91) v1(104.37,26.37) v1(104.37,23.83) v1(104.37,21.29) v1(104.37,18.75) v1(104.37,16.21) v1(104.37,13.67) v1(104.37,11.13) v1(104.37,8.59) v1(104.37,6.05) v1(104.37,3.51)
GND_EARTH: length 28.3
  TOP w0.635: J12.13 32.38,66.14 ; J12.13 32.38,63.18 ; J12.13 32.96,64.66 ; 16.38,63.18 J12.14 ; J12.14 15.81,64.66 ; J12.14 16.38,66.14
  L2_GND w0.635: J12.13 32.96,64.66 ; J12.13 32.38,63.18 ; J12.13 32.38,66.14 ; 15.81,64.66 J12.14 ; J12.14 16.38,63.18 ; J12.14 16.38,66.14
  L3_S2 w0.635: 15.81,64.66 J12.14 ; J12.14 16.38,66.14 ; J12.14 16.38,63.18 ; J12.13 32.96,64.66 ; J12.13 32.38,63.18 ; J12.13 32.38,66.14
  BOTTOM w0.635: 15.81,64.66 J12.14 ; J12.14 16.38,63.18 ; J12.14 16.38,66.14 ; J12.13 32.38,66.14 ; J12.13 32.96,64.66 ; J12.13 32.38,63.18
  vias: v1(0.71,63.83) v1(0.66,59.18) v1(0.76,66.52) v1(0.81,57.86) v1(0.84,51.94) v1(15.24,67.18) v1(15.24,65.53) v1(15.24,63.63) v1(15.24,61.72) v1(15.24,60.07) v1(15.37,59.18) v1(20.78,53.8) v1(22.61,54.61) v1(23.09,53.59) v1(25.53,54.61) v1(27.36,54.61) v1(27.58,53.37) v1(29.11,54.61) v1(29.24,53.34) v1(33.63,59.87) v1(33.66,65.79) v1(33.66,64.26) v1(33.66,62.74) v1(33.66,60.96)
VBAT_RTC: length 3.3
  TOP w0.381: D4.A 89.64,12.67 90.17,13.21 J3.1
VCC1V5_DVP: length 39.8
  BOTTOM w0.305: 54.94,5.39 54.58,5.74 53.9,5.74 53.67,5.97 J10.3
  BOTTOM w0.508: C73.2 81.78,3.74 81.23,4.29 81.23,4.37 80.92,4.67 76.74,4.67 75.04,6.37 70.38,6.37 69.72,5.71 69.72,4.32 67.69,2.29 64.9,2.29 64.59,2.6 64.59,4.63 63.83,5.39 54.94,5.39 ; C73.2 82.04,3.17 82.1,3.12 R63.2 ; C73.2 82.05,3.73 U9.5 83.5,3.73 84,3.22 C394.2
VCC1V8_DVP: length 62.8
  TOP w0.508: v1(87.81,1.65) v1(82.27,1.65)
  BOTTOM w0.305: J10.4 54.17,7.34 53.76,7.75 53.21,7.75 ; Q8.1 46.85,9.64 46.98,9.52 47.44,9.52
  BOTTOM w0.508: v1(87.81,1.65) R59.2 87.81,2.61 86.87,3.56 C68.2 86.88,3.73 U8.5 ; 48.54,8.03 49.02,8.51 49.78,8.51 50.16,8.89 ; 48.54,8.03 47.94,8.63 R1223.2 47.81,9.53 47.8,9.52 47.44,9.52 ; 48.54,8.03 48.54,6.88 47.64,5.99 47.64,2.8 49.13,1.32 66.47,1.32 66.8,1.65 v1(82.27,1.65) ; 53.21,7.75 52.64,7.75 R1222.2 51.87,8.51 50.54,8.51 50.16,8.89 ; 50.16,8.89 Q9.1
VCC2V8_DVP:
  vias: v1(54.28,3.68) v1(54.85,3.68) v1(76.96,3.3) v1(77.6,3.3)
VCC3V3_SD_OUT: length 11.6
  TOP w0.508: v1(42.06,53.29) 35.51,53.29 35.03,52.81 M1.38
  BOTTOM w0.508: v1(42.06,53.29) 42.31,53.54 C156.2 43.06,53.54 J21.4
VCC3V3_SYS: length 121.7
  TOP w0.381: v1(12.78,20.81) 12.78,20.81 11.05,22.54 11.05,23.62 11.43,24 R10.2 ; v1(70.12,12.77) 70.04,12.77 69.98,12.7 68.99,12.7 68.97,12.68 68.48,12.68 68.46,12.7 v1(66.74,12.7) ; D3.A v1(88.66,10.74)
  TOP w0.508: v1(69.88,15.98) 69.34,16.52 69.34,16.89 69.23,16.99 69.23,18.98 69.04,19.17 69.04,19.23 68.67,19.59 v1(68.67,20.16) ; J46.1 9.26,33.35 9.13,33.48 5.41,33.48 5.19,33.25 5.19,22.5 5.71,21.97 10.69,21.97 12.72,19.94 14.1,19.94
  L3_S2 w0.381: v1(95.71,8.86) 95.61,8.86 93.73,10.74 v1(88.66,10.74)
  L3_S2 w0.508: 67.98,7.53 68.52,6.99 75.31,6.99 76.05,6.24 94.76,6.24 95.71,7.19 v1(95.71,8.86) ; 67.98,7.53 67.98,9.36 66.76,10.58 66.76,12.68 v1(66.74,12.7) ; 67.98,7.53 66.6,6.15 55.19,6.15 53.47,7.87 51.05,7.87 49.02,9.91 45.2,9.91 v1(44.25,8.96)
  BOTTOM w0.381: v1(66.74,12.7) 66.76,12.68 66.76,12.01 67.06,11.71 R42.2 R40.2 ; v1(12.78,20.81) 12.9,20.81 12.98,20.73 13.65,20.73 15.83,18.54 v1(16.59,18.54) v1(17.27,18.54)
  BOTTOM w0.508: R46.1 70.23,12.66 v1(70.12,12.77) 70.12,14.76 69.98,14.91 69.98,15.88 v1(69.88,15.98)
  vias: v1(16.59,17.86) v1(41.43,20.65) v1(42.04,20.83) v1(61.37,33.4) v1(61.65,32.84) v1(68.71,20.85) v1(80.57,31.88) v1(81.28,31.88) v1(86.87,40.64) v1(87.1,48.01) v1(87.44,40.64) v1(87.68,48.01)
VCC5V0_USB_FE_D1: length 1.6
  L3_S2 w0.635: 101.46,22.91 J13.1 102.23,22.13
  vias: v1(97.03,21.08) v1(97.03,20.32)
VCC5V0_USB_FE_D2: length 1.6
  BOTTOM w0.635: 96.77,32.8 J36.1 96,33.58
VCC5V0_USB_FE_D3: length 2.3
  BOTTOM w0.635: J37.1 96.77,23.69 ; J37.1 96,22.91 ; J37.1 96.77,22.13
VCC5V0_USB_FE_D4: length 2.3
  L3_S2 w0.635: 101.46,12.24 J38.1 ; J38.1 102.23,13.02 ; J38.1 102.23,11.46
  vias: v1(94.49,14.86) v1(94.74,14.1)
VCC5V0_USB_HOST1:
  vias: v1(46.48,59.79) v1(47.24,59.79)
VCC5V0_USB_HOST2: length 1.6
  L3_S2 w0.635: 102.23,32.8 J39.1 101.46,33.58
  vias: v1(94.29,27.05) v1(94.87,27.05)
VCC5V0_USB_OTG: length 9.1
  TOP w0.508: v1(61.09,60.33) 64.01,60.33 64.33,60.01 64.83,60.01
  BOTTOM w0.508: v1(61.09,60.33) 61.09,58.69 58.67,56.28 R121.2
  vias: v1(65.55,59.76) v1(65.55,59.12) v1(65.53,58.55) v1(66.16,59.76) v1(66.16,59.12) v1(66.17,58.55) v1(73.53,58.55) v1(73.53,57.98) v1(73.56,57.4) v1(74.17,58.55) v1(74.17,57.98) v1(74.17,57.4)
VCC5V_HDMI_TX: length 5.2
  TOP w0.381: v1(86.55,62.05) 86.55,62.04 86.48,61.97 J6.18
  BOTTOM w0.381: v1(86.55,62.05) 85.13,60.64 C47.2 84.56,60.66 D13.C
VCC5V_SYS: length 43.9
  TOP w0.254: R3.2 C6.2 20.72,33.4 20.98,33.15 20.98,31.94 20.6,31.56 20.6,29.44 20.19,29.03 20.19,28.42 19.65,27.87 C10.2
  TOP w0.381: v1(69.22,27.05) 69.06,26.9 69.06,21.92 69.34,21.64 69.34,19.8 69.66,19.48 71.4,19.48 71.65,19.23 71.65,16.81 71.07,16.22 v1(70.55,16.22)
  BOTTOM w0.203: R232.2 77.81,55.14 77.15,55.8 76.05,55.8 75.06,54.81 74.09,54.81 73.42,54.14 C369.2
  BOTTOM w0.381: R47.1 71.25,12.57 70.72,13.1 70.72,14.97 70.55,15.14 v1(70.55,16.22) ; v1(62.74,33.91) 64.21,33.91 64.86,33.26 64.86,30.97 65.27,30.55 65.27,30.26 65.74,29.79 65.74,28.46 66.13,28.07 66.14,28.07 66.55,27.66 68.61,27.66 v1(69.22,27.05)
  vias: v1(18.14,26.41) v1(18.18,27.1) v1(18.72,26.42) v1(18.75,27.1) v1(19.33,27.08) v1(19.3,26.42) v1(55.58,43.76) v1(56.16,43.76) v1(56.73,43.76) v1(56.89,36.8) v1(56.9,36.2) v1(57.34,43.76) v1(57.46,36.8) v1(57.47,36.2) v1(57.91,43.76) v1(58.04,36.8) v1(58.05,36.2) v1(58.49,43.76) v1(71.7,50.28) v1(71.68,49.71) v1(71.7,49.13) v1(72.39,50.28) v1(72.36,49.71) v1(72.36,49.13)
VCC-AMP:
  vias: v1(83.92,28.73) v1(83.92,27.51) v1(83.92,26.92) v1(83.95,28.12)
VCC_1V8_OUT: length 169.5
  TOP w0.508: v1(67.44,39.72) 66.29,40.86 66.29,45.61 66.22,45.69 66.22,46.23 66.29,46.31 v1(66.29,48.93) ; R6.1 19.6,41.91 21.25,40.27 21.25,38.02 21.48,37.79 21.48,31.73 21.13,31.37 21.13,29.07 20.71,28.65 20.71,25.9 21.34,25.27 21.34,23.66 20.8,23.12 20.8,18.84 19.87,17.91 v1(18.8,17.91) 18.8,17.53 18.92,17.4 R14.2 ; R73.1 83.19,32.36 83.89,31.66 85,31.66 86.14,32.79 86.57,32.79 87.25,33.47 v1(87.25,33.78) ; v1(78.26,46.91) 78.26,43.54 78.29,43.5 R66.1 ; v1(46.65,48.93) 46.65,46.25 45.85,45.44 45.85,27.94 44.2,26.29 44.2,20.95 43.69,20.45 v1(42.8,20.45) ; v1(77.75,36.93) 78.29,37.47 C85.2 C86.2 R65.1 ; U10.22 v1(81.81,36.52) ; M1.166 72.99,44.06 72.67,43.74 71.95,43.74 71.61,44.08 71.61,46.49 71.26,46.85 v1(71.18,46.85)
  BOTTOM w0.508: v1(18.8,17.91) 19.62,17.08 20.91,17.08 20.97,17.14 26.72,17.14 27.44,16.42 32.87,16.42 34.21,15.09 37.47,15.09 38.54,16.16 38.54,16.19 v1(42.8,20.45) ; v1(87.25,33.78) 87.25,33.89 84.62,36.52 v1(81.81,36.52) 78.16,36.52 v1(77.75,36.93) 74.29,36.93 71.55,39.67 67.48,39.67 v1(67.44,39.72) ; v1(78.26,46.91) 78.04,46.91 77.89,46.77 73.45,46.77 73.38,46.83 71.21,46.83 v1(71.18,46.85) 71.18,46.92 69.18,48.93 v1(66.29,48.93) 53.93,48.93 53.91,48.91 46.67,48.91 v1(46.65,48.93)
VCC_3V3_HUB: length 2.1
  TOP w0.305: R296.1 v1(77.39,17.65) ; v1(79.11,15.4) 79.09,15.42 78.8,15.42 78.06,14.68 R297.1
  vias: v1(81.01,21.03) v1(81.39,20.6) v1(85.5,15.9) v1(85.52,15.29) v1(85.72,20.57) v1(86.4,20.57) v1(88.85,19.79)
VCC_5V: length 58.5
  TOP w0.305: Q1.1 82.69,54.47 82.41,54.19 v1(82.17,54.19)
  TOP w0.381: v1(20.19,42.8) C13.2 R4.2
  TOP w0.508: J42.1 2.77,48.97
  TOP w0.635: 3.57,48.97 J42.1 2.79,49.75 ; 2.79,16.19 J40.1 ; J40.1 3.57,16.97 ; J40.1 2.79,17.75 ; J40.1 2.02,16.97
  TOP w1.016: 1.52,28.88 1.52,18.24 J40.1 ; 1.52,28.88 2.77,27.64 J41.1 ; 1.52,28.88 1.55,28.91 1.55,39.57 ; 1.55,39.57 1.55,47.75 2.77,48.97 ; 1.55,39.57 2.79,38.32 J43.1
  L3_S2 w0.635: 2.79,48.2 J42.1 ; J42.1 2.79,49.75 ; J42.1 3.57,48.97 ; J42.1 2.02,48.97
  BOTTOM w0.381: D13.A 78.69,60.66 v1(76.96,58.93) ; v1(20.19,42.8) 19.98,42.59 v1(19.98,37.77) ; D12.A 80.9,53.34 81.75,54.19 v1(82.17,54.19)
  vias: v1(1.7,49.5) v1(1.98,50.14) v1(2.95,50.19) v1(4.04,49.45) v1(4.04,48.72) v1(4.06,50.16) v1(9.37,9.6) v1(9.37,9.04) v1(19.98,37.02) v1(19.98,36.45) v1(20.57,37.62) v1(20.57,37.02) v1(20.57,36.45) v1(59.05,59.69) v1(59.05,59.05) v1(59.63,59.69) v1(59.63,59.05) v1(60.21,59.69) v1(60.21,59.05) v1(75.69,58.93) v1(75.69,58.23) v1(76.33,58.93) v1(76.33,58.23) v1(76.96,58.23) v1(77.7,21.38) v1(77.95,21.89) v1(80.98,25.27) v1(81.53,24.99) v1(82.17,24.99) v1(86.18,25.1) v1(86.28,14.5) v1(86.76,25.1) v1(86.86,14.53) v1(87.14,13.29) v1(87.35,25.13) v1(87.74,13.29) v1(87.92,25.08)
VCC_12V:
  vias: v1(11.66,33.66) v1(11.66,33.03) v1(12.24,33.66) v1(12.24,33.02) v1(12.36,49.64) v1(12.93,49.64) v1(13.63,49.58) v1(13.72,48.77) v1(13.72,47.88) v1(14.2,49.58) v1(14.4,48.79) v1(14.4,47.9) v1(14.86,49.43) v1(15.04,48.77) v1(15.06,47.9) v1(25.91,5.05) v1(25.91,4.38) v1(26.67,5.05) v1(26.67,4.38) v1(72.75,5.51) v1(72.75,4.84) v1(73.42,5.51) v1(73.42,4.82)
VCC_DCIN: length 13
  BOTTOM w0.635: 6.11,63.87 J2.3 6.89,64.64 ; 4.11,63.87 J2.4 3.33,64.64
  BOTTOM w1.016: J2.3 J2.4 2.44,62.97 J1.4 ; J1.4 3.77,61.43 ; J1.4 2.44,59.76 3.12,59.08
VCC_LEDA_TX1: length 1
  BOTTOM w0.508: v1(43.03,3.71) 43.13,3.81 U6.5
  vias: v1(30.57,5.21) v1(31.15,5.21) v1(53.72,5.22) v1(54.31,5.19)
VCC_LEDK_TX1: length 9.2
  L3_S2 w0.508: v1(42.75,5.41) 43.48,6.14 46.15,6.14 47.57,7.57 v1(47.57,7.75)
  BOTTOM w0.381: v1(42.75,5.41) 42.55,5.62 R48.1
  BOTTOM w0.508: R51.2 R50.2 47.08,6.95 47.57,7.44 v1(47.57,7.75)
VCC_RMII: length 48.3
  TOP w0.381: v1(38.61,18.8) 38.28,19.12 38.28,24.13 33.73,28.68 33.73,28.93 33.66,29 33.66,29.16 v1(33.35,29.46) ; v1(28.06,20.32) v1(28.06,21.97) 28.06,22.02 28.83,22.79 28.83,23.62 28.37,24.08 v1(28.06,24.08) 28.7,24.72 28.7,25.53 28.19,26.04 v1(28.06,26.04) 28.06,27.41 29.1,28.45 30.99,28.45 31.22,28.68 v1(31.22,28.69)
  TOP w0.508: v1(38.61,18.8) 38.35,18.54 35.94,18.54 v1(35.31,19.18) 34.67,18.54 33.02,18.54 v1(32.38,19.18)
  BOTTOM w0.254: 33.54,19.57 U11.14
  BOTTOM w0.381: v1(32.38,19.18) 31.98,19.18 31.6,18.8 R1211.1 C381.2 33.15,18.53 33.15,19.18 33.54,19.57 ; v1(31.22,28.69) 31.23,28.7 32.33,28.7 33.1,29.46 v1(33.35,29.46) 33.71,29.46 R1226.2 34.09,28.82 34.8,28.12 R1225.1 ; R1218.1 v1(28.06,26.04) ; R1213.2 C391.2 39.57,19.46 38.9,18.8 v1(38.61,18.8) ; v1(35.31,19.18) 35.43,19.05 35.43,18.04 34.98,17.58 R1219.2 ; R1203.2 v1(28.06,20.32) ; v1(28.06,24.08) R1204.1 ; R1202.2 28.26,22.17 v1(28.06,21.97)
VCCA_RMII: length 14.2
  TOP w0.381: v1(35.22,26.2) 37.69,23.73 v1(37.69,21.35)
  BOTTOM w0.254: 37.32,21.36 U11.7
  BOTTOM w0.279: U11.30 35.04,25.54
  BOTTOM w0.381: v1(35.22,26.2) 35.22,26.38 34.8,26.8 R1225.2 C389.2 C390.2 32.97,26.85 33.53,26.29 34.29,26.29 35.04,25.54 ; C380.2 38.56,21.36 37.69,21.36 v1(37.69,21.35) 37.58,21.35 37.57,21.36 37.32,21.36
VCCIO5_IN: length 43.2
  TOP w0.508: M1.228 32.58,44.49 37.35,39.73 37.35,37.1 33.58,33.33 33.58,30.89 32.41,29.72 32.41,24.91 30.92,23.43 30.92,19.75 31.62,19.05 31.62,15.87 v1(31.5,15.75)
  BOTTOM w0.508: v1(31.5,15.75) 30.69,14.94 28.03,14.94 26.53,16.44 25.02,16.44 24.38,15.8 C29.2
  vias: v1(22.73,15.77) v1(22.73,15.09)
VDD_3V3: length 181
  TOP w0.254: R29.2 85.69,51.52 v1(85.23,51.52)
  TOP w0.381: v1(38.99,49.67) 39.36,49.67 39.45,49.58 39.46,49.58 39.65,49.39 39.65,49.38 39.75,49.28 39.75,48.25 40.52,47.48 40.52,45.13 40.03,44.65 40.03,40.59 38.46,39.01 38.46,36.68 34.92,33.15 v1(34.92,29.97) 34.92,29.17 39.3,24.8 39.3,19.97 39.71,19.56 39.71,18.34 38.83,17.46 37.66,17.46 37.17,16.98 37.17,16.73 36.83,16.39 v1(36.83,15.75) ; v1(94.36,50.1) 93.65,50.1 R163.1 ; v1(87.48,63.12) 87.63,62.97 87.63,58.17 87.87,57.92 87.87,52.99 v1(87.59,52.7) 87.59,51.33 v1(87.54,51.28)
  L3_S2 w0.381: 16.21,19.43 18.14,19.43 20.05,17.52 20.05,17.49 20.39,17.15 20.42,17.15 20.56,17.01 26.91,17.01 27.41,16.51 33.4,16.51 34.76,15.16 36.24,15.16 v1(36.83,15.75)
  BOTTOM w0.127: Q2.1 v1(85.23,51.52)
  BOTTOM w0.254: v1(87.54,51.28) 87.23,51.28 Q3.1 ; Q3.1 86.19,52.32 85.22,52.32 84.57,51.68 Q2.1 ; Q3.1 86.84,51.38 86.84,50.21 R33.1
  BOTTOM w0.305: Q2.1 84.57,50.92 84.45,50.8 84.45,50.18 R31.1
  BOTTOM w0.381: R170.2 93.91,63.18 ; 93.91,63.18 98.62,63.18 99.19,62.61 R164.2 ; 93.91,63.18 92.91,63.18 92.55,63.53 88.93,63.53 88.52,63.12 v1(87.48,63.12) 86.7,63.9 84.98,63.9 84.71,63.63 74.3,63.63 72.24,61.57 70.1,61.57 69.72,61.95 R415.1 R19.1 ; v1(34.92,29.97) 34.99,29.9 R1226.1 ; R334.1 47.88,12.06 47.57,12.38 R333.1 48.13,12.7 v1(48.26,12.83) ; R344.1 38.86,49.66 38.87,49.67 v1(38.99,49.67) ; 90.75,50.1 v1(94.36,50.1)
  BOTTOM w0.432: v1(87.59,52.7) 88.15,52.7 94.76,46.09 95.17,45.08 97.17,43.09 97.17,43.05 97.53,42.69 97.57,42.69 100.74,39.52 100.74,32.69 101.22,32.21 101.22,16.71 100.74,16.23 100.74,11.53 98.2,9 97.95,8.89 97.26,8.43 96.35,8.05 v1(93.37,8.05)
  vias: v1(12.47,10.97) v1(13.13,11.21) v1(14.22,11.81) v1(14.92,24.52) v1(15.6,24.51) v1(15.67,12.7) v1(16.08,13.31) v1(16.76,32.77) v1(16.76,4.83) v1(16.76,4.06) v1(17.4,4.83) v1(17.48,32.84) v1(18.03,4.83) v1(18.03,4.06) v1(18.67,4.83) v1(34.72,5.33) v1(35.23,5.03) v1(89.38,22.45) v1(89.38,21.88) v1(92.67,8.71) v1(92.68,7.98) v1(93.32,8.69)
VDD_RTC: length 38
  TOP w0.305: v1(85.94,13.28) 86.32,12.89 D4.C D3.C ; v1(72.08,16.39) 72.16,16.48 72.16,21.11 71.04,22.23 v1(70.74,22.23)
  BOTTOM w0.305: v1(72.08,16.39) 72.63,16.39 72.97,16.05 76.97,16.05 78.71,14.32 85.03,14.32 85.94,13.41 v1(85.94,13.28) ; U5.8 66.54,24.29 C32.2 65.89,26.64 66.19,26.95 68.49,26.95 69.11,26.32 69.11,25.1 69.57,24.64 70.43,24.64 70.74,24.33 v1(70.74,22.23)
CAM_CLKOUT0_MIPI_CSI: length 125.7
  TOP w0.127: v1(4.73,13.46) 4.73,11.81 9.93,6.6 v1(11.81,6.6) ; v1(4.76,20.21) 4.04,20.93 4.04,37.11 4.45,37.52 4.45,39.42 5.18,40.16 5.18,49 6.35,50.16 8.41,50.16 10.04,51.8 10.04,51.9 10.15,52.01 10.25,52.01 11.58,53.34 19.18,53.34 20.83,51.69 20.83,49.35 18.6,47.13 R17.2 C62.2 R16.1
  BOTTOM w0.127: v1(4.73,13.46) 4.76,13.5 v1(4.76,20.21) ; J10.9 56.67,7.31 55.2,8.79 53.67,8.79 52.53,9.93 51.61,9.93 51.03,10.52 51.03,11.53 50.39,12.17 50.39,12.59 49.27,13.72 47.12,13.72 46.61,13.21 46.02,13.21 39.95,7.13 36.85,7.13 36.4,6.68 32.49,6.68 32.05,7.11 28.96,7.11 28.45,6.6 23.88,6.6 23.37,6.1 17.78,6.1 17.27,6.6 v1(11.81,6.6)
CIF_SCL: length 12.3
  TOP w0.127: v1(51.44,9.21) 51.33,9.32 48.07,9.32 47.77,9.02 45.98,9.02 45.88,9.12 v1(45.86,9.12)
  BOTTOM w0.127: J10.7 55.67,7.42 54.93,8.16 53.43,8.16 52.38,9.21 R1222.1 v1(51.44,9.21) ; v1(45.86,9.12) Q8.2
CIF_SDA: length 12.2
  BOTTOM w0.127: J10.8 56.17,7.28 55.04,8.42 53.54,8.42 53.16,8.79 53.16,8.94 52.42,9.68 51.03,9.68 50.6,10.1 50.6,11.28 50.39,11.5 49.27,11.5 49.16,11.39 Q9.2 49.16,10.17 48.84,9.85 R1223.1
CKXTALIN: length 7.3
  BOTTOM w0.203: U11.32 36.04,25.37 36.53,25.86 36.53,26.56 C386.1 36.52,27.67 36.52,28.32 36.72,28.53 37.76,28.53 38.94,29.71 XT4.3
CKXTALOUT: length 8.9
  BOTTOM w0.203: XT4.1 37.85,30.54 37.85,29.08 37.62,28.86 36.59,28.86 36.19,28.46 36.19,27.61 C387.2 36.2,26.59 36.2,26.24 35.54,25.58 U11.31
COLOR_ENABLE: length 4.4
  TOP w0.127: J5.6 25.07,6.1 24.8,5.83 23.74,5.83 v1(22.99,5.08)
  BOTTOM w0.127: TP2.1 22.23,4.32 v1(22.99,5.08)
EDP_HPDIN_M1: length 80.2
  TOP w0.127: v1(19.68,7.87) 20.08,7.48 20.94,7.48 21.07,7.35 J5.14 ; v1(65.56,16.68) 65.24,17.01 65.24,17.95 64.97,18.21 64.97,34.12 65.35,34.49 71.4,34.49 72.97,36.06 M1.158
  BOTTOM w0.127: v1(19.68,7.87) 20.45,7.11 22.89,7.11 23.37,7.59 28.08,7.59 28.49,8 32.47,8 32.88,7.59 35.98,7.59 36.66,8.27 39.79,8.27 45.65,14.13 46.16,14.13 46.73,14.7 48.89,14.7 50.83,16.64 63.08,16.64 63.5,16.21 64.6,16.21 65.07,16.68 v1(65.56,16.68)
EDP_ON: length 20.2
  TOP w0.127: v1(23.57,10.79) J5.9 ; M1.94 32.8,10.79 v1(35.56,10.79)
  BOTTOM w0.127: v1(35.56,10.79) 35.28,11.07 23.82,11.07 23.57,10.83 v1(23.57,10.79)
EDP_TX_AUXN: length 69.1
  TOP w0.102: v1(18.25,10.04) 18.03,9.83 18.03,9.44 18.14,9.34 C34.2 ; M1.22 51.03,51.03 50.66,50.66 50.66,50.17 50.14,49.66 47.6,49.66 47.5,49.56 47.5,46 46.79,45.29 46.79,25.54 46.42,25.18 46.42,24.49 v1(46.63,24.28)
  BOTTOM w0.102: v1(18.25,10.04) 18.03,10.25 18.03,10.69 18.27,10.92 22.33,10.92 22.97,11.57 36.59,11.57 37.12,12.1 38.32,12.1 46.13,19.91 46.13,23.39 46.42,23.69 46.42,24.07 v1(46.63,24.28)
EDP_TX_AUXN_: length 2.5
  TOP w0.102: C34.1 18.14,8.44 18.03,8.34 18.03,7.87 17.78,7.62 17.55,7.62 17.45,7.52 17.45,7.32 17.57,7.2 J5.21
EDP_TX_AUXP: length 69.1
  TOP w0.102: v1(45.96,24.28) 46.17,24.49 46.17,25.28 46.53,25.65 46.53,45.39 47.24,46.1 47.24,49.66 47.49,49.91 50.04,49.91 50.41,50.28 50.41,50.69 50.03,51.06 M1.23 ; C35.2 17.68,9.34 17.78,9.44 17.78,9.83 v1(17.57,10.04)
  BOTTOM w0.102: v1(17.57,10.04) 17.78,10.25 17.78,10.79 18.16,11.18 22.22,11.18 22.87,11.82 36.48,11.82 37.02,12.36 38.21,12.36 45.87,20.02 45.87,23.5 46.17,23.79 46.17,24.07 v1(45.96,24.28)
EDP_TX_AUXP_: length 2.5
  TOP w0.102: J5.22 17.07,7.16 17.19,7.29 17.19,7.62 17.44,7.87 17.67,7.87 17.78,7.98 17.78,8.34 17.68,8.44 C35.1
EDP_TX_D0N: length 68.9
  TOP w0.102: v1(15.41,10.08) 15.62,9.87 15.62,9.44 15.52,9.34 C38.2 ; v1(43.41,29.51) 43.62,29.72 43.86,29.72 44.11,29.97 44.11,45.83 43.66,46.29 43.66,49.05 42.66,50.05 42.66,50.53 43.03,50.91 M1.30
  BOTTOM w0.102: v1(43.41,29.51) 43.62,29.72 43.96,29.72 44.96,28.72 44.96,20.19 37.72,12.95 36.6,12.95 36.09,12.45 22.41,12.45 21.91,11.94 17.02,11.94 15.62,10.54 15.62,10.29 v1(15.41,10.08)
EDP_TX_D0N_: length 2.2
  TOP w0.102: C38.1 15.52,8.44 15.62,8.34 15.62,7.62 15.69,7.55 15.69,7.31 15.57,7.19 J5.25
EDP_TX_D0P: length 68.9
  TOP w0.102: v1(43.41,30.18) 43.62,29.97 43.76,29.97 43.86,30.07 43.86,45.73 43.4,46.18 43.4,48.95 42.41,49.94 42.41,50.56 42.03,50.93 M1.31 ; v1(16.09,10.08) 15.88,9.87 15.88,9.44 15.98,9.34 C39.2
  BOTTOM w0.102: v1(43.41,30.18) 43.62,29.97 44.07,29.97 45.21,28.83 45.21,20.09 37.82,12.7 36.7,12.7 36.19,12.19 22.52,12.19 22.01,11.68 17.12,11.68 15.88,10.44 15.88,10.29 v1(16.09,10.08)
EDP_TX_D0P_: length 2.2
  TOP w0.102: J5.24 16.07,7.17 15.95,7.29 15.95,7.65 15.88,7.73 15.88,8.34 15.98,8.44 C39.1
EDP_TX_D1N: length 70.7
  TOP w0.102: C36.2 13.23,9.34 13.34,9.44 13.34,9.77 v1(13.12,9.98) ; v1(43.51,27.86) 43.72,28.07 44.2,28.07 44.96,28.83 44.96,45.85 45.82,46.71 45.82,50.24 45.51,50.55 44.8,50.55 44.7,50.65 44.7,50.79 45.03,51.13 M1.28
  BOTTOM w0.102: v1(13.12,9.98) 13.34,10.19 13.34,10.41 13.84,10.92 14.88,10.92 16.67,12.71 21.6,12.71 21.97,13.08 35.71,13.08 36.22,13.59 37.36,13.59 44.07,20.3 44.07,27.97 43.97,28.07 43.72,28.07 v1(43.51,27.86)
EDP_TX_D1N_: length 2.8
  TOP w0.102: C36.1 13.2,8.44 13.34,8.31 13.34,7.87 13.59,7.62 14.05,7.62 14.19,7.48 14.19,7.34 14.07,7.21 J5.28
EDP_TX_D1P: length 70.7
  TOP w0.102: M1.29 44.03,51.17 44.44,50.76 44.44,50.54 44.69,50.29 45.41,50.29 45.57,50.13 45.57,46.82 44.7,45.95 44.7,28.93 44.09,28.32 43.72,28.32 v1(43.51,28.53) ; v1(13.8,9.98) 13.59,9.77 13.59,9.44 13.69,9.34 C37.2
  BOTTOM w0.102: v1(43.51,28.53) 43.72,28.32 44.07,28.32 44.32,28.07 44.32,20.19 37.46,13.34 36.32,13.34 35.81,12.83 22.08,12.83 21.71,12.46 16.78,12.46 14.99,10.67 13.95,10.67 13.59,10.31 13.59,10.21 13.8,10 v1(13.8,9.98)
EDP_TX_D1P_: length 2.8
  TOP w0.102: J5.27 14.57,7.15 14.45,7.27 14.45,7.58 14.16,7.87 13.69,7.87 13.59,7.98 13.59,8.32 13.71,8.44 C37.1
FE1.1_DM1: length 25.6
  TOP w0.114: U26.3 80.36,18.79 79.97,18.4 77.46,18.4 76.97,18.89 76.97,20.29 77.09,20.41 77.36,20.41 77.47,20.52 77.47,20.75 77.36,20.87 77.09,20.87 76.97,20.98 76.97,22.01 78.12,23.15 78.81,23.15 79.35,23.69 88.51,23.69 90.07,25.25 90.07,25.73 90.83,26.49 90.83,27.3 90.99,27.47 91.16,27.47 R131.1
FE1.1_DM1_: length 15.9
  TOP w0.114: R131.2 92.72,27.55 D31.10 D31.1 94.55,27.55 94.71,27.7 95.24,27.7 95.92,28.38 95.92,29.41 96.75,30.24 98.71,30.24 99.2,29.75 99.2,27.2 100.61,25.79 102.12,25.79 102.23,25.67 J13.2
FE1.1_DM2: length 28.8
  TOP w0.114: R146.1 91.06,29.34 90.76,29.34 90.72,29.31 90.72,28.24 90.47,27.98 90.46,27.98 90.12,27.64 90.12,26.85 89.41,26.14 89.41,25.55 88.15,24.29 78.98,24.29 78.56,23.87 77.92,23.87 76.4,22.35 76.4,17.82 77.13,17.09 80.04,17.09 80.23,17.29 U26.6
FE1.1_DM2_: length 12.9
  TOP w0.114: J36.2 96.77,36.42 96.66,36.53 96.18,36.53 95.76,36.11 95.76,32.54 95.87,32.43 96.02,32.43 96.14,32.31 96.14,32.08 96.02,31.97 95.87,31.97 95.76,31.85 95.76,31.62 95.87,31.51 95.92,31.51 96.04,31.4 96.04,31.17 95.92,31.05 95.87,31.05 95.76,30.94 95.76,30.55 95.28,30.07 95.28,29.46 95.02,29.2 94.76,29.2 94.6,29.05 D31.4 D31.7 93.23,29.11 92.5,29.11 R146.2
